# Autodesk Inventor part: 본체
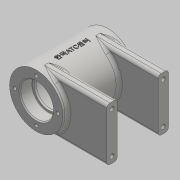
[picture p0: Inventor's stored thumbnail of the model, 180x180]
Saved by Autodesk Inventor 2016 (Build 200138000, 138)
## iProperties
Created: 2020-07
Part Number: 본체
Material: 일반
Document SubType Name: Modeling
Designer: 605-15
Density: 1 g/cm^3
Appearance: 기본값
Mass: 113.054 g
Surface Area: 357.567 cm^2
Volume: 113.054 cm^3
Author: 605-15
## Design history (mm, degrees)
sketch "스케치1"
  geometry: 1 further point
sketch "스케치2"
  geometry: C1 r 26 at (0, 0); 1 further point
  constraints: 1 centre point, 1 coincident
  dimensions: "d0" = 52 diameter of C1
extrude "돌출1" new body sketch "스케치2" stored distance "d1" = 70; taper "d2" = 0 deg
sketch "스케치3"
  geometry: L1 (26, 35)-(-26, 35) reference; L2 (0, 35)-(0, -35); L3 (-26, -35)-(26, -35) reference; L4 (0, 35)-(-16, 35); L5 (-16, 35)-(-16, 23); L6 (-16, 23)-(-14, 23); L7 (-14, 23)-(-14, 21); L8 (-14, 21)-(-21, 21); L9 (-21, 21)-(-21, -21); L10 (-21, -21)-(-14, -21); L11 (-14, -21)-(-14, -23); L12 (-14, -23)-(-16, -23); L13 (-16, -23)-(-16, -35); L14 (-16, -35)-(0, -35); 1 further point
  constraints: 24 end point, 9 perpendicular, 2 midpoint, 2 point on line, 1 vertical
  dimensions: "d3" = 32 diameter of L5 L2; "d4" = 28 diameter of L7 L2; "d5" = 42 diameter of L9 L2; "d6" = 28 diameter of L11 L2; "d7" = 32 diameter of L13 L2; "d9" = 2 distance of L6.end L7.end; "d10" = 2 distance of L10.end L11.end; "d11" = 12 distance of L4.end L5.end; "d12" = 12 distance of L12.end L13.end
revolve "회전1" sketch "스케치3" stored, may be unused: angle "d13" = 90 deg
sketch "스케치4"
  geometry: L1 (0, 0)-(-21, 0); C1 r 26 at (0, 0) reference
  constraints: 2 end point, 1 horizontal
  dimensions: "d14" = 21 distance of L1.start L1.end
hole "구멍1" sketch "스케치4" at (-21, 0) diameter "d15" = 3.242; stored, may be unused: countersink angle "d19" = 90 deg, drill point angle "d21" = 118 deg; dims "d16" = 8, "d17" = 4, "d18" = 2, "d20" = 10
node "작업 평면1"
sketch "스케치5"
  geometry: C1 r 5 at (0, 0); 1 further point
  constraints: 1 centre point, 1 coincident
  dimensions: "d26" = 10 diameter of C1
extrude "돌출2" join sketch "스케치5" stored distance "d27" = 70; taper "d28" = 0 deg
hole "구멍2" diameter "d31" = 5.188; stored, may be unused: countersink angle "d35" = 90 deg, drill point angle "d37" = 118 deg; dims "d29" = 10, "d30" = 10, "d32" = 12, "d33" = 4, "d34" = 2, "d36" = 16
node "작업 평면2"
sketch "스케치6"
  geometry: L1 (30, 26)-(20, 26); L2 (20, 26)-(20, -26); L3 (20, -26)-(30, -26); L4 (30, -26)-(30, 26); L5 (-20, 26)-(-30, 26); L6 (-30, 26)-(-30, -26); L7 (-30, -26)-(-20, -26); L8 (-20, -26)-(-20, 26); 3 further points
  constraints: 16 end point, 4 parallel, 2 horizontal, 2 horizontal alignment, 2 midpoint, 2 perpendicular
  dimensions: "d40" = 10 distance of L2.end L3.end; "d41" = 10 distance of L6.end L7.end; "d42" = 52 distance of L1.end L2.end; "d43" = 52 distance of L5.end L6.end; "d44" = 30 distance from line of L4 point (0, 0); "d45" = 30 distance from line of L6 point (0, 0)
extrude "돌출3" join sketch "스케치6" stored distance "d46" = 70; taper "d47" = 0 deg
sketch "스케치7"
  geometry: L1 (0, 0)-(-27.251, -9.919); L2 (0, 0)-(-64, 0); L3 (-64, -26)-(-64, 26) reference; C1 r 16 at (0, 0) reference; 1 further point
  constraints: 4 end point, 1 midpoint
  dimensions: "d48" = 20 deg angle of L1 L2; "d49" = 29 distance of L1.start L1.end
node "작업 평면3"
sketch "스케치8"
  geometry: C1 r 6 at (0, 0); 1 further point
  constraints: 1 centre point, 1 coincident
  dimensions: "d50" = 12 diameter of C1
extrude "돌출4" join sketch "스케치8" stored distance "d51" = 70; taper "d52" = 0 deg
sketch "스케치9"
  geometry: C1 r 6 at (0, 0) reference
hole "구멍3" sketch "스케치9" at (0, 0) diameter "d53" = 5.188; stored, may be unused: countersink angle "d57" = 90 deg, drill point angle "d59" = 118 deg; dims "d54" = 12, "d55" = 4, "d56" = 2, "d58" = 16
fillet "모깎기2" dims "d60" = 2
chamfer "모따기1" distance "d61" = 1; stored, may be unused: second distance "d62" = 2, angle "d63" = 45 deg
fillet "모깎기3" dims "d64" = 3
fillet "모깎기4" dims "d65" = 0.3
sketch "스케치10"
  geometry: L1 (26, 30)-(-26, 30) reference; 3 further points
  constraints: 1 horizontal alignment
  dimensions: "d66" = 5 distance from line of point (-20, 25) L1; "d67" = 20 horizontal distance of point (0, 0) point (20, 25); "d68" = 20 horizontal distance of point (0, 0) point (-20, 25)
hole "구멍4" sketch "스케치10" at (-20, 25), (20, 25) diameter "d69" = 4.134; stored, may be unused: countersink angle "d73" = 90 deg, drill point angle "d75" = 118 deg; dims "d70" = 8, "d71" = 4, "d72" = 2, "d74" = 10
fillet "모깎기5" dims "d76" = 3
fillet "모깎기6" dims "d77" = 3
node "작업 평면4"
sketch "스케치11"
  geometry: L1 (-26, -35)-(26, -35) reference; 2 further points
  constraints: 1 other
  dimensions: "d79" = 35 distance from line of L1 point (0, 0); "d80" = 26 horizontal distance of L1.start point (0, 0)
feature "엠보싱1" sketch "스케치11" dims "d0" = 52, "d13" = 90 deg, "d81" = 0.5, "d82" = 0
node "솔리드1"
pattern_circular "원형 패턴1" dims angle "d23" = 360 deg
mirror "대칭1"
mirror "대칭2"
other parameters: "d25" = -29, "d39" = 64, "d78" = 49.5
